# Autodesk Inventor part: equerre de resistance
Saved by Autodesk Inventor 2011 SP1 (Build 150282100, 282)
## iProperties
Created: 2010-12
Part Number: equerre de resistance
Document SubType Name: Modeling
Designer: eric
Density: 1 g/cm^3
Author: eric
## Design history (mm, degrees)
feature "Base1"
node "Solide1"
node "Corps solides"
node "Corps surfaciques"
